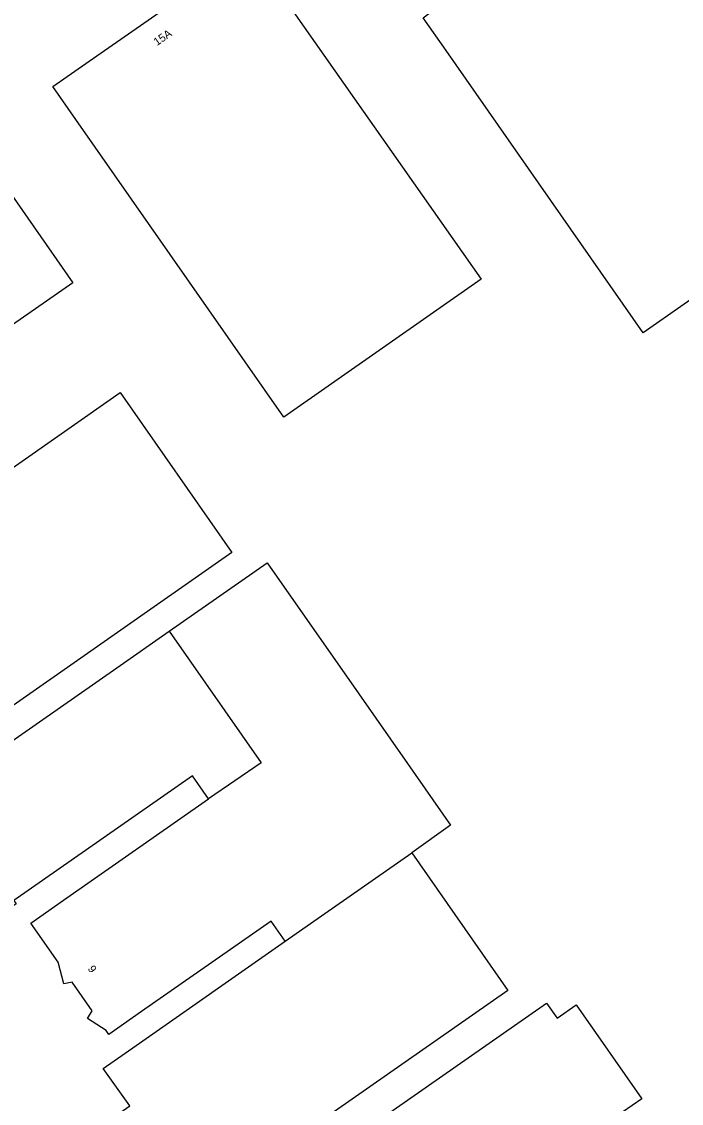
# Model space of a CAD drawing. Extents: x 156651 to 158072, y 387631 to 388990.
# Drawn here: x 157240.2 to 157322.6, y 388207.5 to 388342.7 of the extents above; entities that cross this region are included whole.
import ezdxf

# ---------------------------------------------------------------- set-up
doc = ezdxf.new("R2010")
doc.units = 0
doc.layers.add('IMGEO_Pand', color=7, linetype='Continuous')
doc.layers.add('IMGEO_Pand_nummerreeks', color=7, linetype='Continuous')

msp = doc.modelspace()

# ---------------------------------------------------------------- linework, layer by layer
at = {"layer": 'IMGEO_Pand'}
for points in [[(157317.87, 388303.82), (157293.23, 388339.07), (157290.36, 388343.17), (157291.08, 388343.68), (157287.75, 388348.47), (157287.25, 388349.18), (157294.45, 388354.22), (157294.96, 388353.48), (157295.5, 388352.73), (157296.66, 388353.56), (157296.11, 388354.31), (157307.71, 388362.39), (157313.83, 388353.63), (157325.01, 388361.46)], [(157272.98, 388293.28), (157246.98, 388330.47), (157244.12, 388334.57), (157249.63, 388338.4), (157259.45, 388345.22), (157260.38, 388343.9), (157261.84, 388344.95), (157261.32, 388345.71), (157269.12, 388351.17), (157271.99, 388347.08), (157297.64, 388310.51), (157272.98, 388293.28)], [(157358.82, 388332.44), (157317.87, 388303.82)], [(157221.64, 388292.69), (157209.9, 388309.47), (157207.04, 388313.57), (157211.17, 388316.44), (157209.2, 388319.35), (157213.55, 388322.37), (157214.13, 388321.52), (157217.97, 388324.16), (157217.38, 388325.05), (157221.71, 388328.09), (157223.72, 388325.21), (157227.88, 388328.1), (157230.77, 388324), (157234.51, 388326.62), (157234.43, 388326.76), (157234.79, 388327), (157237.66, 388322.9), (157246.63, 388310.05), (157221.64, 388292.69)], [(157224.66, 388276.88), (157252.51, 388296.33), (157266.46, 388276.35), (157235.8, 388254.93), (157231.7, 388252.07), (157226.17, 388259.99), (157223.71, 388258.28), (157221.49, 388261.46), (157221.33, 388261.35), (157220.99, 388261.83), (157222.14, 388262.64), (157220.93, 388264.37), (157219.79, 388263.57), (157219.44, 388264.05), (157219.61, 388264.17), (157215.35, 388270.29)], [(157258.66, 388266.55), (157270.9, 388275.09), (157282.34, 388258.71), (157288.43, 388250), (157293.8, 388242.31), (157288.94, 388238.83)], [(157263.55, 388245.58), (157261.55, 388248.45), (157239.24, 388232.88), (157239.53, 388232.45), (157234.79, 388229.14), (157230.68, 388226.28), (157227.61, 388230.68), (157231.64, 388233.5), (157231.01, 388234.39), (157235.57, 388237.57), (157229.53, 388246.22), (157233.64, 388249.08), (157234.95, 388250), (157252.11, 388261.97), (157258.66, 388266.55)], [(157258.66, 388266.55), (157270.15, 388250.09), (157263.55, 388245.58)], [(157273.14, 388227.81), (157271.4, 388230.3), (157255.21, 388219.01), (157251.11, 388216.15), (157250.76, 388216.63), (157248.44, 388218.13), (157249.03, 388219.09), (157246.52, 388222.69), (157245.47, 388222.46), (157244.78, 388225.17), (157241.36, 388230.07), (157245.46, 388232.93), (157263.55, 388245.58)], [(157288.94, 388238.83), (157300.96, 388221.65), (157259.85, 388192.94), (157255.75, 388190.07), (157247.04, 388202.52), (157253.75, 388207.23), (157250.42, 388211.88), (157254.51, 388214.75), (157273.14, 388227.81)], [(157273.14, 388227.81), (157288.94, 388238.83)], [(157261.99, 388189.49), (157266.09, 388192.36), (157305.78, 388220.06), (157307.1, 388218.17), (157309.5, 388219.83), (157317.68, 388208.11), (157315.29, 388206.44), (157316.06, 388205.33), (157295.22, 388190.82)]]:
    msp.add_lwpolyline(points, dxfattribs=at)

# ---------------------------------------------------------------- texts
at = {"layer": 'IMGEO_Pand_nummerreeks'}
for s, rotation, p in [('15A', 34.8052, (157257.13, 388339.62)), ('9', 304.8958, (157248.43, 388224.35))]:
    msp.add_text(s, height=1, rotation=rotation, dxfattribs=at).set_placement(p)

doc.saveas('drawing.dxf')
